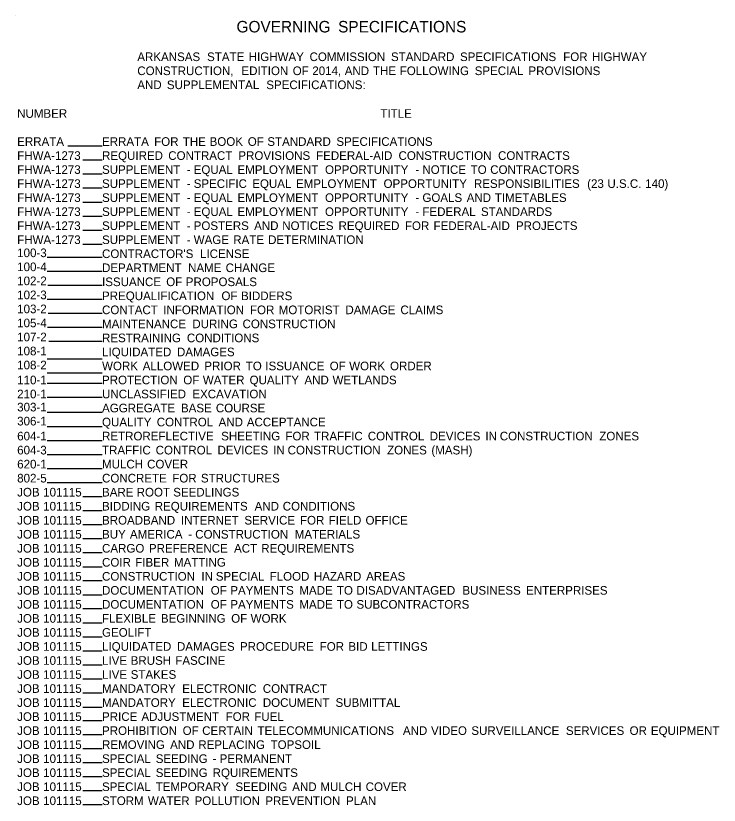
# Model space of a CAD drawing. Extents: x 1955708 to 1956002, y 566396 to 566594.
# Drawn here: x 1955707.7 to 1955805.5, y 566448.7 to 566558.4 of the extents above; entities that cross this region are included whole.
import ezdxf

# ---------------------------------------------------------------- set-up
doc = ezdxf.new("R2010")
doc.units = 0
doc.layers.add('Default', color=7, linetype='Continuous')
doc.layers.add('R_No Plot', color=7, linetype='Continuous')

msp = doc.modelspace()

# ---------------------------------------------------------------- linework, layer by layer
at = {"layer": 'Default'}
for p, q in [((1955714.96, 566540.36), (1955719.7, 566540.36)), ((1955717.04, 566538.41), (1955719.7, 566538.41)), ((1955717.04, 566536.45), (1955719.7, 566536.45)), ((1955717.04, 566534.5), (1955719.7, 566534.5)), ((1955717.04, 566532.54), (1955719.7, 566532.54)), ((1955717.04, 566530.59), (1955719.7, 566530.59)), ((1955717.04, 566528.65), (1955719.7, 566528.65)), ((1955717.04, 566526.69), (1955719.7, 566526.69)), ((1955712.09, 566524.88), (1955719.7, 566524.88)), ((1955712.09, 566522.93), (1955719.7, 566522.93)), ((1955712.15, 566520.98), (1955719.7, 566520.98)), ((1955712.09, 566519.04), (1955719.7, 566519.04)), ((1955712.22, 566517.09), (1955719.7, 566517.09)), ((1955712.1, 566515.13), (1955719.7, 566515.13)), ((1955712.32, 566513.19), (1955719.7, 566513.19)), ((1955712.08, 566510.73), (1955719.7, 566510.73)), ((1955712.08, 566508.78), (1955719.7, 566508.78)), ((1955712.08, 566507.34), (1955719.7, 566507.34)), ((1955712.08, 566505.39), (1955719.7, 566505.39)), ((1955712.08, 566503.31), (1955719.7, 566503.31)), ((1955712.08, 566501.35), (1955719.7, 566501.35)), ((1955712.08, 566499.4), (1955719.7, 566499.4)), ((1955712.08, 566497.46), (1955719.7, 566497.46)), ((1955712.08, 566495.51), (1955719.7, 566495.51)), ((1955712.08, 566493.55), (1955719.7, 566493.55)), ((1955717.03, 566491.6), (1955719.7, 566491.6)), ((1955717.03, 566489.66), (1955719.7, 566489.66)), ((1955717.03, 566487.7), (1955719.7, 566487.7)), ((1955717.03, 566485.76), (1955719.7, 566485.76)), ((1955717.03, 566483.8), (1955719.7, 566483.8)), ((1955717.03, 566481.84), (1955719.7, 566481.84)), ((1955717.03, 566479.9), (1955719.7, 566479.9)), ((1955717.03, 566477.95), (1955719.7, 566477.95)), ((1955717.03, 566476.01), (1955719.7, 566476.01)), ((1955717.03, 566474.05), (1955719.7, 566474.05)), ((1955717.03, 566472.11), (1955719.7, 566472.11)), ((1955717.03, 566470.15), (1955719.7, 566470.15)), ((1955717.03, 566468.19), (1955719.7, 566468.19)), ((1955717.03, 566466.25), (1955719.7, 566466.25)), ((1955717.03, 566464.31), (1955719.7, 566464.31)), ((1955717.03, 566462.33), (1955719.7, 566462.33)), ((1955717.03, 566460.46), (1955719.7, 566460.46)), ((1955717.03, 566458.51), (1955719.7, 566458.51)), ((1955717.03, 566456.56), (1955719.7, 566456.56)), ((1955717.03, 566454.62), (1955719.7, 566454.62)), ((1955717.03, 566452.67), (1955719.7, 566452.67)), ((1955717.03, 566450.72), (1955719.7, 566450.72)), ((1955717.03, 566448.78), (1955719.7, 566448.78))]:
    msp.add_line(p, q, dxfattribs=at)
at = {"layer": 'R_No Plot'}
msp.add_line((1955707.71, 566558.44), (1955707.71, 566558.44), dxfattribs=at)

# ---------------------------------------------------------------- texts
at = {"layer": 'Default'}
for s, height, p in [('GOVERNING', 1.6, (1955738.4, 566556.12)), (' SPECIFICATIONS', 1.6, (1955751.93, 566556.12)), ('           ARKANSAS', 1.2, (1955719.7, 566552.14)), (' STATE', 1.2, (1955733.86, 566552.14)), (' HIGHWAY', 1.2, (1955739.65, 566552.14)), (' COMMISSION', 1.2, (1955748.11, 566552.14)), (' STANDARD', 1.2, (1955759.43, 566552.14)), (' SPECIFICATIONS', 1.2, (1955769.03, 566552.14)), (' FOR', 1.2, (1955783.38, 566552.14)), (' HIGHWAY', 1.2, (1955787.37, 566552.14)), ('           CONSTRUCTION,', 1.2, (1955719.7, 566550.19)), (' EDITION', 1.2, (1955738.64, 566550.19)), (' OF', 1.2, (1955745.77, 566550.19)), (' 2014,', 1.2, (1955748.49, 566550.19)), (' AND', 1.2, (1955753, 566550.19)), (' THE', 1.2, (1955756.92, 566550.19)), (' FOLLOWING', 1.2, (1955760.65, 566550.19)), (' SPECIAL', 1.2, (1955771.07, 566550.19)), (' PROVISIONS', 1.2, (1955778.55, 566550.19)), ('           AND', 1.2, (1955719.7, 566548.24)), (' SUPPLEMENTAL', 1.2, (1955728.27, 566548.24)), (' SPECIFICATIONS:', 1.2, (1955742.09, 566548.24)), ('NUMBER', 1.2, (1955707.9, 566544.25)), ('TITLE', 1.2, (1955758.41, 566544.25)), ('ERRATA', 1.2, (1955707.9, 566540.35)), ('ERRATA', 1.2, (1955719.7, 566540.35)), (' FOR', 1.2, (1955726.5, 566540.35)), (' THE', 1.2, (1955730.48, 566540.35)), (' BOOK', 1.2, (1955734.21, 566540.35)), (' OF', 1.2, (1955739.52, 566540.35)), (' STANDARD', 1.2, (1955742.24, 566540.35)), (' SPECIFICATIONS', 1.2, (1955751.84, 566540.35)), ('FHWA-1273', 1.2, (1955707.9, 566538.4)), ('REQUIRED', 1.2, (1955719.7, 566538.4)), (' CONTRACT', 1.2, (1955728.46, 566538.4)), (' PROVISIONS', 1.2, (1955738.21, 566538.4)), (' FEDERAL-AID', 1.2, (1955749.02, 566538.4)), (' CONSTRUCTION', 1.2, (1955760.48, 566538.4)), (' CONTRACTS', 1.2, (1955774.32, 566538.4)), ('FHWA-1273', 1.2, (1955707.9, 566536.45)), ('SUPPLEMENT', 1.2, (1955719.7, 566536.45)), (' EQUAL', 1.2, (1955732, 566536.45)), (' EMPLOYMENT', 1.2, (1955738.09, 566536.45)), (' OPPORTUNITY', 1.2, (1955750.26, 566536.45)), (' NOTICE', 1.2, (1955763.8, 566536.45)), (' TO', 1.2, (1955770.51, 566536.45)), (' CONTRACTORS', 1.2, (1955773.23, 566536.45)), (' -', 1.2, (1955731.03, 566536.45)), (' -', 1.2, (1955762.83, 566536.45)), ('FHWA-1273', 1.2, (1955707.9, 566534.5)), ('SUPPLEMENT', 1.2, (1955719.7, 566534.5)), (' SPECIFIC', 1.2, (1955732, 566534.5)), (' EQUAL', 1.2, (1955740.14, 566534.5)), (' EMPLOYMENT', 1.2, (1955746.23, 566534.5)), (' OPPORTUNITY', 1.2, (1955758.4, 566534.5)), (' RESPONSIBILITIES', 1.2, (1955770.96, 566534.5)), (' (23', 1.2, (1955786.71, 566534.5)), (' U.S.C.', 1.2, (1955789.53, 566534.5)), (' 140)', 1.2, (1955794.78, 566534.5)), (' -', 1.2, (1955731.03, 566534.5)), ('FHWA-1273', 1.2, (1955707.9, 566532.55)), ('SUPPLEMENT', 1.2, (1955719.7, 566532.55)), (' -', 1.2, (1955731.03, 566532.55)), (' EQUAL', 1.2, (1955732, 566532.55)), (' EMPLOYMENT', 1.2, (1955738.09, 566532.55)), (' OPPORTUNITY', 1.2, (1955750.26, 566532.55)), (' -', 1.2, (1955762.83, 566532.55)), (' GOALS', 1.2, (1955763.8, 566532.55)), (' AND', 1.2, (1955769.96, 566532.55)), (' TIMETABLES', 1.2, (1955773.87, 566532.55)), ('FHWA-1273', 1.2, (1955707.9, 566530.6)), ('SUPPLEMENT', 1.2, (1955719.7, 566530.6)), (' EQUAL', 1.2, (1955732, 566530.6)), (' EMPLOYMENT', 1.2, (1955738.09, 566530.6)), (' OPPORTUNITY', 1.2, (1955750.26, 566530.6)), (' FEDERAL', 1.2, (1955763.8, 566530.6)), (' STANDARDS', 1.2, (1955771.94, 566530.6)), (' -', 1.2, (1955731.03, 566530.6)), (' -', 1.2, (1955762.83, 566530.6)), ('FHWA-1273', 1.2, (1955707.9, 566528.65)), ('SUPPLEMENT', 1.2, (1955719.7, 566528.65)), (' POSTERS', 1.2, (1955732, 566528.65)), (' AND', 1.2, (1955740.4, 566528.65)), (' NOTICES', 1.2, (1955744.31, 566528.65)), (' REQUIRED', 1.2, (1955752.14, 566528.65)), (' FOR', 1.2, (1955761.37, 566528.65)), (' FEDERAL-AID', 1.2, (1955765.35, 566528.65)), (' PROJECTS', 1.2, (1955776.81, 566528.65)), (' -', 1.2, (1955731.03, 566528.65)), ('FHWA-1273', 1.2, (1955707.9, 566526.7)), ('SUPPLEMENT', 1.2, (1955719.7, 566526.7)), (' WAGE', 1.2, (1955732, 566526.7)), (' RATE', 1.2, (1955737.5, 566526.7)), (' DETERMINATION', 1.2, (1955742.35, 566526.7)), (' -', 1.2, (1955731.03, 566526.7)), ('100-3', 1.2, (1955707.9, 566524.88)), ("CONTRACTOR'S", 1.2, (1955719.7, 566524.75)), (' LICENSE', 1.2, (1955732.88, 566524.75)), ('100-4', 1.2, (1955707.9, 566522.93)), ('DEPARTMENT', 1.2, (1955719.7, 566522.8)), (' NAME', 1.2, (1955731.22, 566522.8)), (' CHANGE', 1.2, (1955736.44, 566522.8)), ('102-2', 1.2, (1955707.9, 566520.98)), ('ISSUANCE', 1.2, (1955719.7, 566520.85)), (' OF', 1.2, (1955728.18, 566520.85)), (' PROPOSALS', 1.2, (1955730.9, 566520.85)), ('102-3', 1.2, (1955707.9, 566519.03)), ('PREQUALIFICATION', 1.2, (1955719.7, 566518.9)), (' OF', 1.2, (1955735.86, 566518.9)), (' BIDDERS', 1.2, (1955738.58, 566518.9)), ('103-2', 1.2, (1955707.9, 566517.08)), ('CONTACT', 1.2, (1955719.7, 566516.95)), (' INFORMATION', 1.2, (1955727.77, 566516.95)), (' FOR', 1.2, (1955739.83, 566516.95)), (' MOTORIST', 1.2, (1955743.82, 566516.95)), (' DAMAGE', 1.2, (1955753.1, 566516.95)), (' CLAIMS', 1.2, (1955760.74, 566516.95)), ('105-4', 1.2, (1955707.9, 566515.13)), ('MAINTENANCE', 1.2, (1955719.7, 566515)), (' DURING', 1.2, (1955731.81, 566515)), (' CONSTRUCTION', 1.2, (1955738.79, 566515)), ('107-2', 1.2, (1955707.9, 566513.18)), ('RESTRAINING', 1.2, (1955719.7, 566513.05)), (' CONDITIONS', 1.2, (1955731.05, 566513.05)), ('108-1', 1.2, (1955707.9, 566511.23)), ('LIQUIDATED', 1.2, (1955719.7, 566511.1)), (' DAMAGES', 1.2, (1955729.67, 566511.1)), ('108-2', 1.2, (1955707.9, 566509.28)), ('WORK', 1.2, (1955719.7, 566509.15)), (' ALLOWED', 1.2, (1955724.91, 566509.15)), (' PRIOR', 1.2, (1955733.48, 566509.15)), (' TO', 1.2, (1955739.24, 566509.15)), (' ISSUANCE', 1.2, (1955741.96, 566509.15)), (' OF', 1.2, (1955750.91, 566509.15)), (' WORK', 1.2, (1955753.62, 566509.15)), (' ORDER', 1.2, (1955759.3, 566509.15)), ('110-1', 1.2, (1955707.9, 566507.2)), ('PROTECTION', 1.2, (1955719.7, 566507.2)), (' OF', 1.2, (1955730.55, 566507.2)), (' WATER', 1.2, (1955733.27, 566507.2)), (' QUALITY', 1.2, (1955739.77, 566507.2)), (' AND', 1.2, (1955747.4, 566507.2)), (' WETLANDS', 1.2, (1955751.31, 566507.2)), ('210-1', 1.2, (1955707.9, 566505.25)), ('UNCLASSIFIED', 1.2, (1955719.7, 566505.25)), (' EXCAVATION', 1.2, (1955731.81, 566505.25)), ('303-1', 1.2, (1955707.9, 566503.43)), ('AGGREGATE', 1.2, (1955719.7, 566503.3)), (' BASE', 1.2, (1955730.23, 566503.3)), (' COURSE', 1.2, (1955735.08, 566503.3)), ('306-1', 1.2, (1955707.9, 566501.48)), ('QUALITY', 1.2, (1955719.7, 566501.35)), (' CONTROL', 1.2, (1955726.86, 566501.35)), (' AND', 1.2, (1955735.46, 566501.35)), (' ACCEPTANCE', 1.2, (1955739.38, 566501.35)), ('604-1', 1.2, (1955707.9, 566499.4)), ('RETROREFLECTIVE', 1.2, (1955719.7, 566499.4)), (' SHEETING', 1.2, (1955735.82, 566499.4)), (' FOR', 1.2, (1955744.75, 566499.4)), (' TRAFFIC', 1.2, (1955748.73, 566499.4)), (' CONTROL', 1.2, (1955756.21, 566499.4)), (' DEVICES', 1.2, (1955764.82, 566499.4)), (' IN', 1.2, (1955772.56, 566499.4)), (' CONSTRUCTION', 1.2, (1955774.56, 566499.4)), (' ZONES', 1.2, (1955788.4, 566499.4)), ('604-3', 1.2, (1955707.9, 566497.45)), ('TRAFFIC', 1.2, (1955719.7, 566497.45)), (' CONTROL', 1.2, (1955726.71, 566497.45)), (' DEVICES', 1.2, (1955735.31, 566497.45)), (' IN', 1.2, (1955743.05, 566497.45)), (' CONSTRUCTION', 1.2, (1955745.06, 566497.45)), (' ZONES', 1.2, (1955758.89, 566497.45)), (' (MASH)', 1.2, (1955765.05, 566497.45)), ('620-1', 1.2, (1955707.9, 566495.5)), ('MULCH', 1.2, (1955719.7, 566495.5)), (' COVER', 1.2, (1955725.52, 566495.5)), ('802-5', 1.2, (1955707.9, 566493.55)), ('CONCRETE', 1.2, (1955719.7, 566493.55)), (' FOR', 1.2, (1955729.02, 566493.55)), (' STRUCTURES', 1.2, (1955733, 566493.55)), ('JOB', 1.2, (1955707.9, 566491.6)), (' 101115', 1.2, (1955711.07, 566491.6)), ('BARE ROOT SEEDLINGS', 1.2, (1955719.7, 566491.6)), ('JOB', 1.2, (1955707.9, 566489.65)), (' 101115', 1.2, (1955711.07, 566489.65)), ('BIDDING', 1.2, (1955719.7, 566489.65)), (' REQUIREMENTS', 1.2, (1955726.58, 566489.65)), (' AND', 1.2, (1955740.47, 566489.65)), (' CONDITIONS', 1.2, (1955744.38, 566489.65)), ('JOB', 1.2, (1955707.9, 566487.7)), (' 101115', 1.2, (1955711.07, 566487.7)), ('BROADBAND', 1.2, (1955719.7, 566487.7)), (' INTERNET', 1.2, (1955730.23, 566487.7)), (' SERVICE', 1.2, (1955739.05, 566487.7)), (' FOR', 1.2, (1955746.78, 566487.7)), (' FIELD', 1.2, (1955750.77, 566487.7)), (' OFFICE', 1.2, (1955755.89, 566487.7)), ('JOB', 1.2, (1955707.9, 566485.75)), (' 101115', 1.2, (1955711.07, 566485.75)), ('BUY', 1.2, (1955719.7, 566485.75)), (' AMERICA', 1.2, (1955723.13, 566485.75)), (' CONSTRUCTION', 1.2, (1955732.21, 566485.75)), (' MATERIALS', 1.2, (1955746.05, 566485.75)), (' -', 1.2, (1955731.24, 566485.75)), ('JOB', 1.2, (1955707.9, 566483.8)), (' 101115', 1.2, (1955711.07, 566483.8)), ('CARGO', 1.2, (1955719.7, 566483.8)), (' PREFERENCE', 1.2, (1955725.77, 566483.8)), (' ACT', 1.2, (1955737.61, 566483.8)), (' REQUIREMENTS', 1.2, (1955741.39, 566483.8)), ('JOB', 1.2, (1955707.9, 566481.85)), (' 101115', 1.2, (1955711.07, 566481.85)), ('COIR', 1.2, (1955719.7, 566481.85)), (' FIBER', 1.2, (1955723.87, 566481.85)), (' MATTING', 1.2, (1955729.25, 566481.85)), ('JOB', 1.2, (1955707.9, 566479.9)), (' 101115', 1.2, (1955711.07, 566479.9)), ('CONSTRUCTION', 1.2, (1955719.7, 566479.9)), (' IN', 1.2, (1955733.07, 566479.9)), (' SPECIAL', 1.2, (1955735.07, 566479.9)), (' FLOOD', 1.2, (1955742.56, 566479.9)), (' HAZARD', 1.2, (1955748.71, 566479.9)), (' AREAS', 1.2, (1955755.98, 566479.9)), ('JOB', 1.2, (1955707.9, 566477.95)), (' 101115', 1.2, (1955711.07, 566477.95)), ('DOCUMENTATION', 1.2, (1955719.7, 566477.95)), (' OF', 1.2, (1955734.37, 566477.95)), (' PAYMENTS', 1.2, (1955737.09, 566477.95)), (' MADE', 1.2, (1955746.69, 566477.95)), (' TO', 1.2, (1955751.91, 566477.95)), (' DISADVANTAGED', 1.2, (1955754.63, 566477.95)), (' BUSINESS', 1.2, (1955769.36, 566477.95)), (' ENTERPRISES', 1.2, (1955778.22, 566477.95)), ('JOB', 1.2, (1955707.9, 566476)), (' 101115', 1.2, (1955711.07, 566476)), ('DOCUMENTATION', 1.2, (1955719.7, 566476)), (' OF', 1.2, (1955734.37, 566476)), (' PAYMENTS', 1.2, (1955737.09, 566476)), (' MADE', 1.2, (1955746.69, 566476)), (' TO', 1.2, (1955751.91, 566476)), (' SUBCONTRACTORS', 1.2, (1955754.63, 566476)), ('JOB', 1.2, (1955707.9, 566474.05)), (' 101115', 1.2, (1955711.07, 566474.05)), ('FLEXIBLE', 1.2, (1955719.7, 566474.05)), (' BEGINNING', 1.2, (1955727.44, 566474.05)), (' OF', 1.2, (1955737.21, 566474.05)), (' WORK', 1.2, (1955739.92, 566474.05)), ('JOB', 1.2, (1955707.9, 566472.1)), (' 101115', 1.2, (1955711.07, 566472.1)), ('GEOLIFT', 1.2, (1955719.7, 566472.1)), ('JOB', 1.2, (1955707.9, 566470.15)), (' 101115', 1.2, (1955711.07, 566470.15)), ('LIQUIDATED', 1.2, (1955719.7, 566470.15)), (' DAMAGES', 1.2, (1955729.67, 566470.15)), (' PROCEDURE', 1.2, (1955738.43, 566470.15)), (' FOR', 1.2, (1955749.52, 566470.15)), (' BID', 1.2, (1955753.51, 566470.15)), (' LETTINGS', 1.2, (1955756.68, 566470.15)), ('JOB', 1.2, (1955707.9, 566468.2)), (' 101115', 1.2, (1955711.07, 566468.2)), ('LIVE', 1.2, (1955719.7, 566468.2)), (' BRUSH', 1.2, (1955723.24, 566468.2)), (' FASCINE', 1.2, (1955729.44, 566468.2)), ('JOB', 1.2, (1955707.9, 566466.25)), (' 101115', 1.2, (1955711.07, 566466.25)), ('LIVE', 1.2, (1955719.7, 566466.25)), (' STAKES', 1.2, (1955723.24, 566466.25)), ('JOB', 1.2, (1955707.9, 566464.3)), (' 101115', 1.2, (1955711.07, 566464.3)), ('MANDATORY', 1.2, (1955719.7, 566464.3)), (' ELECTRONIC', 1.2, (1955730.4, 566464.3)), (' CONTRACT', 1.2, (1955741.61, 566464.3)), ('JOB', 1.2, (1955707.9, 566462.35)), (' 101115', 1.2, (1955711.07, 566462.35)), ('MANDATORY', 1.2, (1955719.7, 566462.35)), (' ELECTRONIC', 1.2, (1955730.4, 566462.35)), (' DOCUMENT', 1.2, (1955741.61, 566462.35)), (' SUBMITTAL', 1.2, (1955751.72, 566462.35)), ('JOB', 1.2, (1955707.9, 566460.4)), (' 101115', 1.2, (1955711.07, 566460.4)), ('PRICE', 1.2, (1955719.7, 566460.4)), (' ADJUSTMENT', 1.2, (1955724.73, 566460.4)), (' FOR', 1.2, (1955736.44, 566460.4)), (' FUEL', 1.2, (1955740.42, 566460.4)), ('JOB', 1.2, (1955707.9, 566458.45)), (' 101115', 1.2, (1955711.07, 566458.45)), ('PROHIBITION', 1.2, (1955719.7, 566458.45)), (' OF', 1.2, (1955730.46, 566458.45)), (' CERTAIN', 1.2, (1955733.18, 566458.45)), (' TELECOMMUNICATIONS', 1.2, (1955740.87, 566458.45)), (' AND', 1.2, (1955761.09, 566458.45)), (' VIDEO', 1.2, (1955765, 566458.45)), (' SURVEILLANCE', 1.2, (1955770.61, 566458.45)), (' SERVICES', 1.2, (1955783.75, 566458.45)), (' OR', 1.2, (1955792.61, 566458.45)), (' EQUIPMENT', 1.2, (1955795.57, 566458.45)), ('JOB', 1.2, (1955707.9, 566456.5)), (' 101115', 1.2, (1955711.07, 566456.5)), ('REMOVING', 1.2, (1955719.7, 566456.5)), (' AND', 1.2, (1955728.72, 566456.5)), (' REPLACING', 1.2, (1955732.64, 566456.5)), (' TOPSOIL', 1.2, (1955742.69, 566456.5)), ('JOB', 1.2, (1955707.9, 566454.55)), (' 101115', 1.2, (1955711.07, 566454.55)), ('SPECIAL', 1.2, (1955719.7, 566454.55)), (' SEEDING', 1.2, (1955726.72, 566454.55)), (' -', 1.2, (1955734.63, 566454.55)), (' PERMANENT', 1.2, (1955735.6, 566454.55)), ('JOB', 1.2, (1955707.9, 566452.6)), (' 101115', 1.2, (1955711.07, 566452.6)), ('SPECIAL', 1.2, (1955719.7, 566452.6)), (' SEEDING', 1.2, (1955726.72, 566452.6)), (' RQUIREMENTS', 1.2, (1955734.63, 566452.6)), ('JOB', 1.2, (1955707.9, 566450.65)), (' 101115', 1.2, (1955711.07, 566450.65)), ('SPECIAL', 1.2, (1955719.7, 566450.65)), (' TEMPORARY', 1.2, (1955726.72, 566450.65)), (' SEEDING', 1.2, (1955737.8, 566450.65)), (' AND', 1.2, (1955745.7, 566450.65)), (' MULCH', 1.2, (1955749.62, 566450.65)), (' COVER', 1.2, (1955755.91, 566450.65)), ('JOB', 1.2, (1955707.9, 566448.7)), (' 101115', 1.2, (1955711.07, 566448.7)), ('STORM', 1.2, (1955719.7, 566448.7)), (' WATER', 1.2, (1955725.63, 566448.7)), (' POLLUTION', 1.2, (1955732.12, 566448.7)), (' PREVENTION', 1.2, (1955741.96, 566448.7)), (' PLAN', 1.2, (1955753.19, 566448.7))]:
    msp.add_text(s, height=height, dxfattribs=at).set_placement(p)

doc.saveas('drawing.dxf')
